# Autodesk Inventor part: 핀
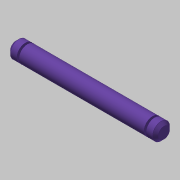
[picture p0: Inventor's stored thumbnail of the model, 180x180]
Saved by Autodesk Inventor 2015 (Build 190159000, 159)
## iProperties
Created: 2019-02
Part Number: 핀
Material: 스테인리스강
Document SubType Name: Modeling
Designer: mduedu
Density: 1 g/cm^3
Appearance: 보라색
Author: mduedu
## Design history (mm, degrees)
sketch "스케치1"
  geometry: L1 (-26, 0)-(26, 0); L2 (26, 0)-(26, 3); L3 (26, 3)-(-26, 3); L4 (-26, 3)-(-26, 0); L5 (-22.7, 3)-(-22, 3); L6 (-22, 3)-(-22, 2); L7 (-22, 2)-(-22.7, 2); L8 (-22.7, 2)-(-22.7, 3); L9 (0, 0)-(0, 3); L10 (22.7, 3)-(22, 3); L11 (22, 3)-(22, 2); L12 (22, 2)-(22.7, 2); L13 (22.7, 2)-(22.7, 3); 1 further point
  constraints: 26 end point, 4 parallel, 4 symmetric about line, 2 horizontal, 2 midpoint, 2 perpendicular, 1 coincident, 1 point on line
  dimensions: "d0" = 52 distance between parallel lines of L2 L4; "d2" = 6 diameter of L3 L1; "d3" = 4 diameter of L7 L1; "d4" = 44 distance between parallel lines of L11 L6; "d5" = 0.7 distance between parallel lines of L6 L8
revolve "회전1" sketch "스케치1" stored, may be unused: angle "d6" = 90 deg
chamfer "모따기1" distance "d7" = 1; stored, may be unused: second distance "d8" = 2, angle "d9" = 45 deg
node "솔리드1"
